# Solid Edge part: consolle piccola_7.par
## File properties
Last saved by: i.fialdini
Revision: 62
Tipo di contenuto documento: 0
Accuracy: 0.990
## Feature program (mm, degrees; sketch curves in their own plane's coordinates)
body "unnamed Body 1"
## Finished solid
Body 1: solid body, 6 faces, 12 edges, 8 vertices.
  Faces by surface: plane 6
  Edges by curve: line 12
Bounding box of the edges (mm): 362.238 x 30.000 x 2.000, from (-175.738, -538.1568, 700.9818) to (186.5, -508.1568, 702.9818).
Planar faces by outward normal: +x 1, +y 1, +z 1, -x 1, -y 1, -z 1
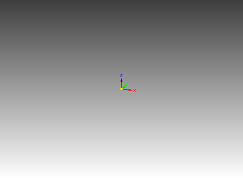
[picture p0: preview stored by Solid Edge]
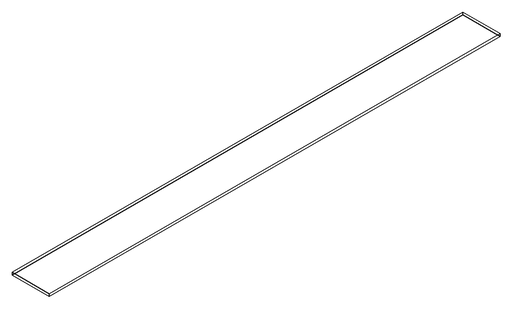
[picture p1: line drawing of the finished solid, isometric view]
